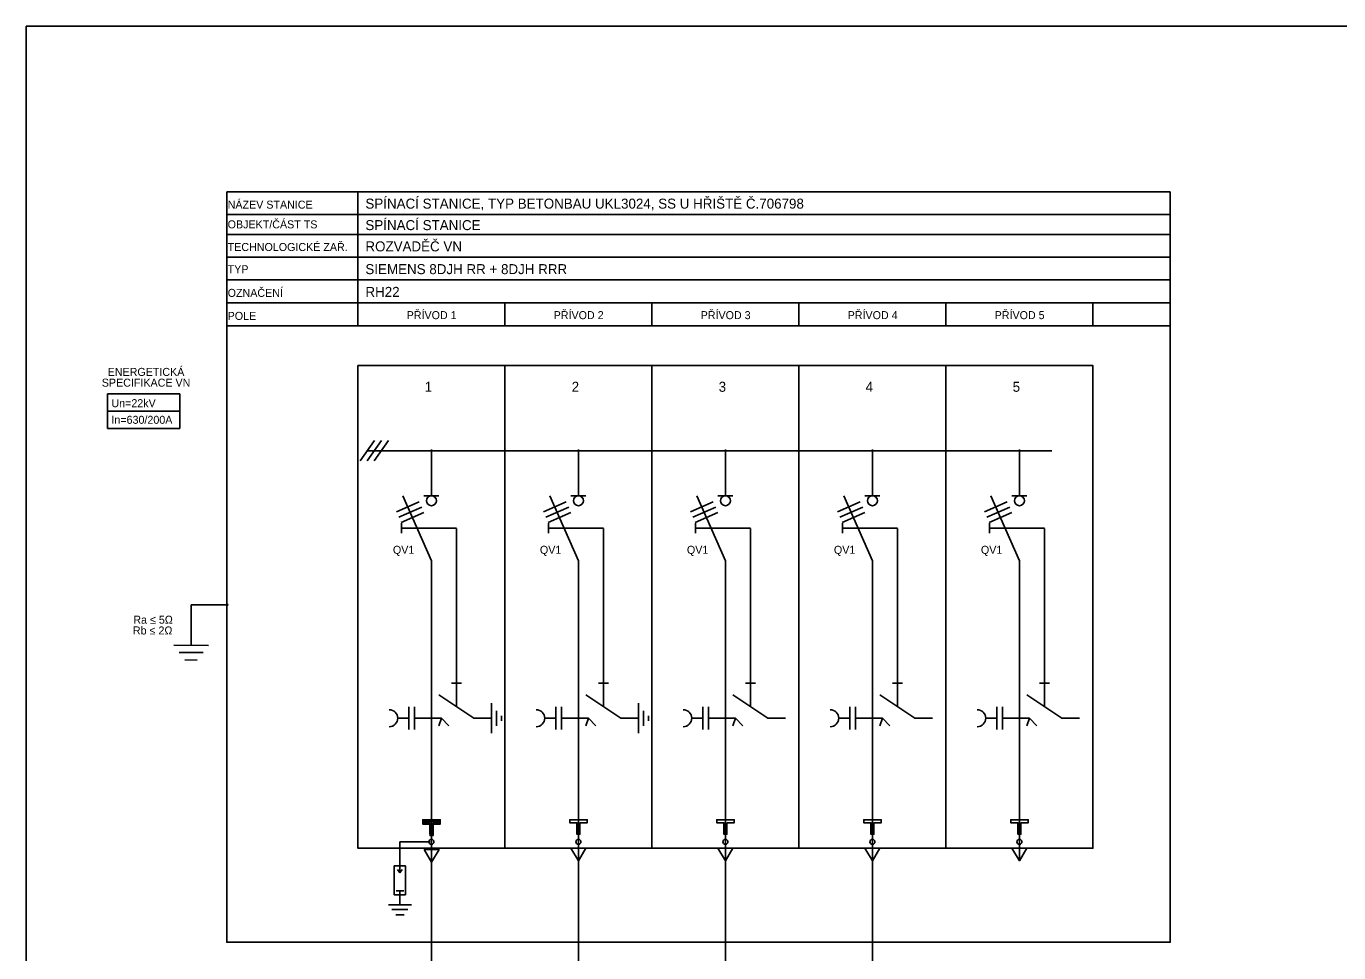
# Model space of a CAD drawing. Extents: x -540906 to -539838, y -1177786 to -1177461.
# Drawn here: x -540048 to -539943, y -1177711.4 to -1177637.3 of the extents above; entities that cross this region are included whole.
import ezdxf

# ---------------------------------------------------------------- set-up
doc = ezdxf.new("R2010")
doc.units = 0
for name, color, linetype in [('_RAZITKO', 7, 'Continuous'), ('FGVN_SCHEMA_VEDENI', 7, 'Continuous'), ('Implicitní', 7, 'Continuous'), ('nv_kabel_rozv_nove', 7, 'Continuous'), ('Popisky', 7, 'Continuous'), ('SILNÁ-ČÁRA', 7, 'Continuous'), ('SLABÁ-ČÁRA', 7, 'Continuous'), ('TEXT-NORMAL', 7, 'Continuous'), ('TEXT-TUČNÝ', 7, 'Continuous'), ('TEXT-TUČNÝ-eon', 7, 'Continuous'), ('ČÁRKOVANÁ', 7, 'Continuous')]:
    doc.layers.add(name, color=color, linetype=linetype)

msp = doc.modelspace()

# ---------------------------------------------------------------- linework, layer by layer
at = {"layer": 'FGVN_SCHEMA_VEDENI'}
for centre, start, end in [((-540015.54, -1177671.25), 0, 180), ((-540015.54, -1177671.25), 180, 0), ((-540003.78, -1177671.25), 0, 180), ((-540003.78, -1177671.25), 180, 0), ((-539992.02, -1177671.25), 0, 180), ((-539992.02, -1177671.25), 180, 0), ((-539980.26, -1177671.25), 0, 180), ((-539980.26, -1177671.25), 180, 0), ((-539968.5, -1177671.25), 0, 180), ((-539968.5, -1177671.25), 180, 0), ((-540031.87, -1177683.58), 0, 180), ((-540031.87, -1177683.58), 180, 0)]:
    msp.add_arc(centre, 0.05, start, end, dxfattribs=at)
at = {"layer": 'Implicitní'}
msp.add_lwpolyline([(-540047.95, -1177637.3), (-539837.95, -1177637.3), (-539837.95, -1177785.8), (-540047.95, -1177785.8)], close=True, dxfattribs=at)
at = {"layer": 'nv_kabel_rozv_nove'}
for p, q in [((-540031.88, -1177683.58), (-540034.76, -1177683.59)), ((-540034.76, -1177683.59), (-540034.76, -1177685.12)), ((-540034.76, -1177685.12), (-540034.76, -1177686.82)), ((-540033.38, -1177686.82), (-540036.14, -1177686.81)), ((-540033.81, -1177687.38), (-540035.72, -1177687.38)), ((-540034.27, -1177688), (-540035.26, -1177687.99))]:
    msp.add_line(p, q, dxfattribs=at)
at = {"layer": 'Popisky'}
for p, q in [((-540003.78, -1177704.05), (-540003.79, -1177722.08)), ((-539992.02, -1177704.05), (-539992.04, -1177740.12)), ((-539980.26, -1177704.05), (-539980.28, -1177740.12)), ((-540015.53, -1177704.15), (-540015.53, -1177723.88))]:
    msp.add_line(p, q, dxfattribs=at)
at = {"layer": 'SILNÁ-ČÁRA'}
for p, q in [((-540015.54, -1177673.25), (-540015.54, -1177671.25)), ((-540003.78, -1177673.25), (-540003.78, -1177671.25)), ((-539992.02, -1177673.25), (-539992.02, -1177671.25)), ((-539980.26, -1177673.25), (-539980.26, -1177671.25)), ((-539968.5, -1177673.25), (-539968.5, -1177671.25)), ((-540015.54, -1177674.85), (-540015.54, -1177673.25)), ((-540003.78, -1177674.85), (-540003.78, -1177673.25)), ((-539992.02, -1177674.85), (-539992.02, -1177673.25)), ((-539980.26, -1177674.85), (-539980.26, -1177673.25)), ((-539968.5, -1177674.85), (-539968.5, -1177673.25)), ((-540017.82, -1177674.85), (-540015.54, -1177680.05)), ((-540016.14, -1177674.85), (-540014.94, -1177674.85)), ((-540006.06, -1177674.85), (-540003.78, -1177680.05)), ((-540004.38, -1177674.85), (-540003.18, -1177674.85)), ((-539994.3, -1177674.85), (-539992.02, -1177680.05)), ((-539992.62, -1177674.85), (-539991.42, -1177674.85)), ((-539982.54, -1177674.85), (-539980.26, -1177680.05)), ((-539980.86, -1177674.85), (-539979.66, -1177674.85)), ((-539970.78, -1177674.85), (-539968.5, -1177680.05)), ((-539969.1, -1177674.85), (-539967.9, -1177674.85)), ((-540015.54, -1177680.05), (-540015.54, -1177681.65)), ((-540003.78, -1177680.05), (-540003.78, -1177681.65)), ((-539992.02, -1177680.05), (-539992.02, -1177681.65)), ((-539980.26, -1177680.05), (-539980.26, -1177681.65)), ((-539968.5, -1177680.05), (-539968.5, -1177681.65)), ((-540015.54, -1177681.65), (-540015.54, -1177704.05)), ((-540003.78, -1177681.65), (-540003.78, -1177704.05)), ((-539992.02, -1177681.65), (-539992.02, -1177704.05)), ((-539980.26, -1177681.65), (-539980.26, -1177704.05)), ((-539968.5, -1177681.65), (-539968.5, -1177704.05)), ((-540016.24, -1177700.77), (-540014.83, -1177700.77)), ((-540016.24, -1177700.77), (-540016.24, -1177701.01)), ((-540016.24, -1177700.77), (-540014.83, -1177700.77)), ((-540016.24, -1177700.77), (-540016.24, -1177701.01)), ((-540016.24, -1177700.88), (-540014.83, -1177700.88)), ((-540016.24, -1177700.88), (-540016.24, -1177701.11)), ((-540016.24, -1177700.88), (-540014.83, -1177700.88)), ((-540016.24, -1177700.88), (-540016.24, -1177701.11)), ((-540014.83, -1177700.77), (-540014.83, -1177701.01)), ((-540014.83, -1177700.77), (-540014.83, -1177701.01)), ((-540014.83, -1177700.88), (-540014.83, -1177701.11)), ((-540014.83, -1177700.88), (-540014.83, -1177701.11)), ((-540004.48, -1177700.77), (-540003.07, -1177700.77)), ((-540004.48, -1177700.77), (-540004.48, -1177701.01)), ((-540004.48, -1177700.77), (-540003.07, -1177700.77)), ((-540004.48, -1177700.77), (-540004.48, -1177701.01)), ((-540003.07, -1177700.77), (-540003.07, -1177701.01)), ((-540003.07, -1177700.77), (-540003.07, -1177701.01)), ((-539992.72, -1177700.77), (-539991.31, -1177700.77)), ((-539992.72, -1177700.77), (-539992.72, -1177701.01)), ((-539992.72, -1177700.77), (-539991.31, -1177700.77)), ((-539992.72, -1177700.77), (-539992.72, -1177701.01)), ((-539991.31, -1177700.77), (-539991.31, -1177701.01)), ((-539991.31, -1177700.77), (-539991.31, -1177701.01)), ((-539980.96, -1177700.77), (-539979.55, -1177700.77)), ((-539980.96, -1177700.77), (-539980.96, -1177701.01)), ((-539980.96, -1177700.77), (-539979.55, -1177700.77)), ((-539980.96, -1177700.77), (-539980.96, -1177701.01)), ((-539979.55, -1177700.77), (-539979.55, -1177701.01)), ((-539979.55, -1177700.77), (-539979.55, -1177701.01)), ((-539969.2, -1177700.77), (-539967.79, -1177700.77)), ((-539969.2, -1177700.77), (-539969.2, -1177701.01)), ((-539969.2, -1177700.77), (-539967.79, -1177700.77)), ((-539969.2, -1177700.77), (-539969.2, -1177701.01)), ((-539967.79, -1177700.77), (-539967.79, -1177701.01)), ((-539967.79, -1177700.77), (-539967.79, -1177701.01)), ((-540016.24, -1177701.01), (-540015.66, -1177701.01)), ((-540016.24, -1177701.01), (-540015.66, -1177701.01)), ((-540016.24, -1177701.11), (-540015.65, -1177701.11)), ((-540016.24, -1177701.11), (-540015.65, -1177701.11)), ((-540015.66, -1177701.01), (-540015.66, -1177701.93)), ((-540015.66, -1177701.01), (-540015.66, -1177701.93)), ((-540015.66, -1177701.01), (-540015.66, -1177701.93)), ((-540015.66, -1177701.01), (-540015.66, -1177701.93)), ((-540015.66, -1177701.93), (-540015.42, -1177701.93)), ((-540015.66, -1177701.93), (-540015.42, -1177701.93)), ((-540015.65, -1177701.11), (-540015.65, -1177702.03)), ((-540015.65, -1177701.11), (-540015.65, -1177702.03)), ((-540015.65, -1177701.11), (-540015.65, -1177702.03)), ((-540015.65, -1177701.11), (-540015.65, -1177702.03)), ((-540015.65, -1177702.03), (-540015.41, -1177702.03)), ((-540015.65, -1177702.03), (-540015.41, -1177702.03)), ((-540015.42, -1177701.01), (-540014.83, -1177701.01)), ((-540015.42, -1177701.01), (-540015.42, -1177701.93)), ((-540015.42, -1177701.01), (-540014.83, -1177701.01)), ((-540015.42, -1177701.01), (-540015.42, -1177701.93)), ((-540015.41, -1177701.11), (-540014.83, -1177701.11)), ((-540015.41, -1177701.11), (-540015.41, -1177702.03)), ((-540015.41, -1177701.11), (-540014.83, -1177701.11)), ((-540015.41, -1177701.11), (-540015.41, -1177702.03)), ((-540004.48, -1177701.01), (-540003.9, -1177701.01)), ((-540004.48, -1177701.01), (-540003.9, -1177701.01)), ((-540003.9, -1177701.01), (-540003.9, -1177701.93)), ((-540003.9, -1177701.01), (-540003.9, -1177701.93)), ((-540003.9, -1177701.01), (-540003.9, -1177701.93)), ((-540003.9, -1177701.01), (-540003.9, -1177701.93)), ((-540003.9, -1177701.93), (-540003.66, -1177701.93)), ((-540003.9, -1177701.93), (-540003.66, -1177701.93)), ((-540003.66, -1177701.01), (-540003.07, -1177701.01)), ((-540003.66, -1177701.01), (-540003.66, -1177701.93)), ((-540003.66, -1177701.01), (-540003.07, -1177701.01)), ((-540003.66, -1177701.01), (-540003.66, -1177701.93)), ((-539992.72, -1177701.01), (-539992.14, -1177701.01)), ((-539992.72, -1177701.01), (-539992.14, -1177701.01)), ((-539992.14, -1177701.01), (-539992.14, -1177701.93)), ((-539992.14, -1177701.01), (-539992.14, -1177701.93)), ((-539992.14, -1177701.01), (-539992.14, -1177701.93)), ((-539992.14, -1177701.01), (-539992.14, -1177701.93)), ((-539992.14, -1177701.93), (-539991.9, -1177701.93)), ((-539992.14, -1177701.93), (-539991.9, -1177701.93)), ((-539991.9, -1177701.01), (-539991.31, -1177701.01)), ((-539991.9, -1177701.01), (-539991.9, -1177701.93)), ((-539991.9, -1177701.01), (-539991.31, -1177701.01)), ((-539991.9, -1177701.01), (-539991.9, -1177701.93)), ((-539980.96, -1177701.01), (-539980.38, -1177701.01)), ((-539980.96, -1177701.01), (-539980.38, -1177701.01)), ((-539980.38, -1177701.01), (-539980.38, -1177701.93)), ((-539980.38, -1177701.01), (-539980.38, -1177701.93)), ((-539980.38, -1177701.01), (-539980.38, -1177701.93)), ((-539980.38, -1177701.01), (-539980.38, -1177701.93)), ((-539980.38, -1177701.93), (-539980.14, -1177701.93)), ((-539980.38, -1177701.93), (-539980.14, -1177701.93)), ((-539980.14, -1177701.01), (-539979.55, -1177701.01)), ((-539980.14, -1177701.01), (-539980.14, -1177701.93)), ((-539980.14, -1177701.01), (-539979.55, -1177701.01)), ((-539980.14, -1177701.01), (-539980.14, -1177701.93)), ((-539969.2, -1177701.01), (-539968.62, -1177701.01)), ((-539969.2, -1177701.01), (-539968.62, -1177701.01)), ((-539968.62, -1177701.01), (-539968.62, -1177701.93)), ((-539968.62, -1177701.01), (-539968.62, -1177701.93)), ((-539968.62, -1177701.01), (-539968.62, -1177701.93)), ((-539968.62, -1177701.01), (-539968.62, -1177701.93)), ((-539968.62, -1177701.93), (-539968.38, -1177701.93)), ((-539968.62, -1177701.93), (-539968.38, -1177701.93)), ((-539968.38, -1177701.01), (-539967.79, -1177701.01)), ((-539968.38, -1177701.01), (-539968.38, -1177701.93)), ((-539968.38, -1177701.01), (-539967.79, -1177701.01)), ((-539968.38, -1177701.01), (-539968.38, -1177701.93)), ((-540018.06, -1177703.16), (-540018.06, -1177705.02)), ((-540018.52, -1177704.45), (-540018.52, -1177706.77)), ((-540017.61, -1177704.45), (-540018.52, -1177704.45)), ((-540018.06, -1177705.02), (-540018.25, -1177704.76)), ((-540018.06, -1177705.02), (-540017.88, -1177704.76)), ((-540017.61, -1177704.45), (-540017.61, -1177706.77)), ((-540017.61, -1177706.77), (-540018.52, -1177706.77)), ((-540017.76, -1177706.45), (-540018.37, -1177706.45)), ((-540018.06, -1177706.45), (-540018.06, -1177707.58)), ((-540017.14, -1177707.58), (-540018.98, -1177707.58)), ((-540017.42, -1177707.95), (-540018.7, -1177707.95)), ((-540017.73, -1177708.37), (-540018.39, -1177708.37))]:
    msp.add_line(p, q, dxfattribs=at)
for points in [[(-540020.67, -1177671.25), (-539965.9, -1177671.25)], [(-540015.42, -1177701.01), (-540014.83, -1177701.01), (-540014.83, -1177700.77), (-540016.24, -1177700.77), (-540016.24, -1177701.01), (-540015.66, -1177701.01), (-540015.66, -1177701.93), (-540015.42, -1177701.93), (-540015.42, -1177701.01)], [(-540015.41, -1177701.11), (-540014.83, -1177701.11), (-540014.83, -1177700.88), (-540016.24, -1177700.88), (-540016.24, -1177701.11), (-540015.65, -1177701.11), (-540015.65, -1177702.03), (-540015.41, -1177702.03), (-540015.41, -1177701.11)], [(-540003.66, -1177701.01), (-540003.07, -1177701.01), (-540003.07, -1177700.77), (-540004.48, -1177700.77), (-540004.48, -1177701.01), (-540003.9, -1177701.01), (-540003.9, -1177701.93), (-540003.66, -1177701.93), (-540003.66, -1177701.01)], [(-539991.9, -1177701.01), (-539991.31, -1177701.01), (-539991.31, -1177700.77), (-539992.72, -1177700.77), (-539992.72, -1177701.01), (-539992.14, -1177701.01), (-539992.14, -1177701.93), (-539991.9, -1177701.93), (-539991.9, -1177701.01)], [(-539980.14, -1177701.01), (-539979.55, -1177701.01), (-539979.55, -1177700.77), (-539980.96, -1177700.77), (-539980.96, -1177701.01), (-539980.38, -1177701.01), (-539980.38, -1177701.93), (-539980.14, -1177701.93), (-539980.14, -1177701.01)], [(-539968.38, -1177701.01), (-539967.79, -1177701.01), (-539967.79, -1177700.77), (-539969.2, -1177700.77), (-539969.2, -1177701.01), (-539968.62, -1177701.01), (-539968.62, -1177701.93), (-539968.38, -1177701.93), (-539968.38, -1177701.01)], [(-540015.65, -1177702.54), (-540018.06, -1177702.54), (-540018.06, -1177703.16)]]:
    msp.add_lwpolyline(points, dxfattribs=at)
for points in [[(-540004.38, -1177703.05), (-540003.18, -1177703.05), (-540003.78, -1177704.05)], [(-539992.62, -1177703.05), (-539991.42, -1177703.05), (-539992.02, -1177704.05)], [(-539980.86, -1177703.05), (-539979.66, -1177703.05), (-539980.26, -1177704.05)], [(-539969.1, -1177703.05), (-539967.9, -1177703.05), (-539968.5, -1177704.05)], [(-540016.13, -1177703.15), (-540014.93, -1177703.15), (-540015.53, -1177704.15)]]:
    msp.add_lwpolyline(points, close=True, dxfattribs=at)
for centre, radius in [((-540015.54, -1177675.25), 0.4), ((-540003.78, -1177675.25), 0.4), ((-539992.02, -1177675.25), 0.4), ((-539980.26, -1177675.25), 0.4), ((-539968.5, -1177675.25), 0.4), ((-540015.54, -1177702.54), 0.2), ((-540015.54, -1177702.54), 0.2), ((-540003.78, -1177702.54), 0.2), ((-540003.78, -1177702.54), 0.2), ((-539992.02, -1177702.54), 0.2), ((-539992.02, -1177702.54), 0.2), ((-539980.26, -1177702.54), 0.2), ((-539980.26, -1177702.54), 0.2), ((-539968.5, -1177702.54), 0.2), ((-539968.5, -1177702.54), 0.2)]:
    msp.add_circle(centre, radius, dxfattribs=at)
at = {"layer": 'SLABÁ-ČÁRA'}
for p, q in [((-540031.92, -1177650.54), (-539956.44, -1177650.54)), ((-540031.92, -1177650.54), (-540031.92, -1177661.26)), ((-540021.42, -1177661.26), (-540021.42, -1177650.54)), ((-539956.44, -1177661.26), (-539956.44, -1177650.54)), ((-540031.92, -1177652.36), (-539956.44, -1177652.36)), ((-540031.92, -1177653.95), (-539956.44, -1177653.95)), ((-540031.92, -1177655.77), (-539956.44, -1177655.77)), ((-540031.92, -1177657.59), (-539956.44, -1177657.59)), ((-540031.84, -1177659.43), (-539956.44, -1177659.43)), ((-540009.66, -1177661.26), (-540009.66, -1177659.43)), ((-539997.9, -1177661.26), (-539997.9, -1177659.43)), ((-539986.14, -1177661.26), (-539986.14, -1177659.43)), ((-539974.38, -1177661.26), (-539974.38, -1177659.43)), ((-539962.62, -1177661.26), (-539962.62, -1177659.43)), ((-540031.92, -1177661.26), (-539956.44, -1177661.26)), ((-540021.25, -1177672.07), (-540020.1, -1177670.43)), ((-540020.69, -1177672.07), (-540019.54, -1177670.43)), ((-540020.12, -1177672.07), (-540018.98, -1177670.43)), ((-540018.34, -1177676.15), (-540016.51, -1177675.34)), ((-540018.15, -1177676.58), (-540016.32, -1177675.77)), ((-540006.58, -1177676.15), (-540004.75, -1177675.34)), ((-540006.39, -1177676.58), (-540004.56, -1177675.77)), ((-539994.82, -1177676.15), (-539992.99, -1177675.34)), ((-539994.63, -1177676.58), (-539992.8, -1177675.77)), ((-539983.06, -1177676.15), (-539981.23, -1177675.34)), ((-539982.87, -1177676.58), (-539981.04, -1177675.77)), ((-539971.3, -1177676.15), (-539969.47, -1177675.34)), ((-539971.11, -1177676.58), (-539969.28, -1177675.77)), ((-540017.97, -1177677), (-540016.14, -1177676.19)), ((-540006.21, -1177677), (-540004.38, -1177676.19)), ((-539994.45, -1177677), (-539992.62, -1177676.19)), ((-539982.69, -1177677), (-539980.86, -1177676.19)), ((-539970.93, -1177677), (-539969.1, -1177676.19)), ((-540017.94, -1177677.05), (-540017.94, -1177677.85)), ((-540017.94, -1177677.45), (-540016.68, -1177677.45)), ((-540016.68, -1177677.45), (-540013.54, -1177677.45)), ((-540013.54, -1177689.85), (-540013.54, -1177677.47)), ((-540006.18, -1177677.05), (-540006.18, -1177677.85)), ((-540006.18, -1177677.45), (-540004.92, -1177677.45)), ((-540004.92, -1177677.45), (-540001.78, -1177677.45)), ((-540001.78, -1177689.85), (-540001.78, -1177677.47)), ((-539994.42, -1177677.05), (-539994.42, -1177677.85)), ((-539994.42, -1177677.45), (-539993.16, -1177677.45)), ((-539993.16, -1177677.45), (-539990.02, -1177677.45)), ((-539990.02, -1177689.85), (-539990.02, -1177677.47)), ((-539982.66, -1177677.05), (-539982.66, -1177677.85)), ((-539982.66, -1177677.45), (-539981.4, -1177677.45)), ((-539981.4, -1177677.45), (-539978.26, -1177677.45)), ((-539978.26, -1177689.85), (-539978.26, -1177677.47)), ((-539970.9, -1177677.05), (-539970.9, -1177677.85)), ((-539970.9, -1177677.45), (-539969.64, -1177677.45)), ((-539969.64, -1177677.45), (-539966.5, -1177677.45)), ((-539966.5, -1177689.85), (-539966.5, -1177677.47)), ((-540013.14, -1177689.85), (-540013.94, -1177689.85)), ((-540013.54, -1177691.71), (-540013.54, -1177689.85)), ((-540001.38, -1177689.85), (-540002.18, -1177689.85)), ((-540001.78, -1177691.71), (-540001.78, -1177689.85)), ((-539989.62, -1177689.85), (-539990.42, -1177689.85)), ((-539990.02, -1177691.71), (-539990.02, -1177689.85)), ((-539977.86, -1177689.85), (-539978.66, -1177689.85)), ((-539978.26, -1177691.71), (-539978.26, -1177689.85)), ((-539966.1, -1177689.85), (-539966.9, -1177689.85)), ((-539966.5, -1177691.71), (-539966.5, -1177689.85)), ((-540014.94, -1177690.77), (-540012.14, -1177692.65)), ((-540010.74, -1177691.45), (-540010.74, -1177693.85)), ((-540003.18, -1177690.77), (-540000.38, -1177692.65)), ((-539998.98, -1177691.45), (-539998.98, -1177693.85)), ((-539991.42, -1177690.77), (-539988.62, -1177692.65)), ((-539979.66, -1177690.77), (-539976.86, -1177692.65)), ((-539967.9, -1177690.77), (-539965.1, -1177692.65)), ((-540017.34, -1177691.75), (-540017.34, -1177693.55)), ((-540016.89, -1177691.75), (-540016.89, -1177693.55)), ((-540010.34, -1177692.05), (-540010.34, -1177693.25)), ((-540009.94, -1177692.45), (-540009.94, -1177692.85)), ((-540005.58, -1177691.75), (-540005.58, -1177693.55)), ((-540005.13, -1177691.75), (-540005.13, -1177693.55)), ((-539998.58, -1177692.05), (-539998.58, -1177693.25)), ((-539998.18, -1177692.45), (-539998.18, -1177692.85)), ((-539993.82, -1177691.75), (-539993.82, -1177693.55)), ((-539993.37, -1177691.75), (-539993.37, -1177693.55)), ((-539982.06, -1177691.75), (-539982.06, -1177693.55)), ((-539981.61, -1177691.75), (-539981.61, -1177693.55)), ((-539970.3, -1177691.75), (-539970.3, -1177693.55)), ((-539969.85, -1177691.75), (-539969.85, -1177693.55)), ((-540018.24, -1177692.65), (-540017.34, -1177692.65)), ((-540016.89, -1177692.65), (-540015.54, -1177692.65)), ((-540015.54, -1177692.65), (-540014.74, -1177692.65)), ((-540014.96, -1177693.25), (-540014.74, -1177692.65)), ((-540014.14, -1177693.25), (-540014.74, -1177692.65)), ((-540010.74, -1177692.65), (-540012.14, -1177692.65)), ((-540006.48, -1177692.65), (-540005.58, -1177692.65)), ((-540005.13, -1177692.65), (-540003.78, -1177692.65)), ((-540003.78, -1177692.65), (-540002.98, -1177692.65)), ((-540003.2, -1177693.25), (-540002.98, -1177692.65)), ((-540002.38, -1177693.25), (-540002.98, -1177692.65)), ((-539998.98, -1177692.65), (-540000.38, -1177692.65)), ((-539994.72, -1177692.65), (-539993.82, -1177692.65)), ((-539993.37, -1177692.65), (-539992.02, -1177692.65)), ((-539992.02, -1177692.65), (-539991.22, -1177692.65)), ((-539991.44, -1177693.25), (-539991.22, -1177692.65)), ((-539990.62, -1177693.25), (-539991.22, -1177692.65)), ((-539987.22, -1177692.65), (-539988.62, -1177692.65)), ((-539982.96, -1177692.65), (-539982.06, -1177692.65)), ((-539981.61, -1177692.65), (-539980.26, -1177692.65)), ((-539980.26, -1177692.65), (-539979.46, -1177692.65)), ((-539979.68, -1177693.25), (-539979.46, -1177692.65)), ((-539978.86, -1177693.25), (-539979.46, -1177692.65)), ((-539975.46, -1177692.65), (-539976.86, -1177692.65)), ((-539971.2, -1177692.65), (-539970.3, -1177692.65)), ((-539969.85, -1177692.65), (-539968.5, -1177692.65)), ((-539968.5, -1177692.65), (-539967.7, -1177692.65)), ((-539967.92, -1177693.25), (-539967.7, -1177692.65)), ((-539967.1, -1177693.25), (-539967.7, -1177692.65)), ((-539963.7, -1177692.65), (-539965.1, -1177692.65))]:
    msp.add_line(p, q, dxfattribs=at)
msp.add_lwpolyline([(-540031.92, -1177661.26), (-539956.44, -1177661.26), (-539956.44, -1177710.57), (-540031.92, -1177710.57)], close=True, dxfattribs=at)
for centre in [(-540018.91, -1177692.65), (-540007.15, -1177692.65), (-539995.39, -1177692.65), (-539983.63, -1177692.65), (-539971.87, -1177692.65)]:
    msp.add_arc(centre, 0.675, 270, 90, dxfattribs=at)
at = {"layer": 'TEXT-NORMAL'}
for p, q in [((-540041.46, -1177666.71), (-540041.46, -1177669.48)), ((-540041.46, -1177666.71), (-540035.67, -1177666.71)), ((-540035.67, -1177666.71), (-540035.67, -1177669.48)), ((-540041.46, -1177668.09), (-540035.67, -1177668.09)), ((-540041.46, -1177669.48), (-540035.67, -1177669.48))]:
    msp.add_line(p, q, dxfattribs=at)
at = {"layer": 'ČÁRKOVANÁ'}
for points in [[(-540021.42, -1177664.45), (-540009.66, -1177664.45), (-540009.66, -1177703.05), (-540021.42, -1177703.05)], [(-540009.66, -1177664.45), (-539997.9, -1177664.45), (-539997.9, -1177703.05), (-540009.66, -1177703.05)], [(-539997.9, -1177664.45), (-539986.14, -1177664.45), (-539986.14, -1177703.05), (-539997.9, -1177703.05)], [(-539986.14, -1177664.45), (-539974.38, -1177664.45), (-539974.38, -1177703.05), (-539986.14, -1177703.05)], [(-539974.38, -1177664.45), (-539962.62, -1177664.45), (-539962.62, -1177703.05), (-539974.38, -1177703.05)]]:
    msp.add_lwpolyline(points, close=True, dxfattribs=at)

# ---------------------------------------------------------------- texts
at = {"layer": '_RAZITKO'}
for s, p in [('NÁZEV STANICE', (-540031.84, -1177651.89)), ('OBJEKT/ČÁST TS', (-540031.84, -1177653.47)), ('TECHNOLOGICKÉ ZAŘ.', (-540031.84, -1177655.28)), ('TYP', (-540031.84, -1177657.06)), ('OZNAČENÍ', (-540031.84, -1177658.95)), ('POLE', (-540031.84, -1177660.79)), ('ENERGETICKÁ ', (-540041.44, -1177665.27)), ('SPECIFIKACE VN', (-540041.91, -1177666.13))]:
    msp.add_text(s, height=0.64, dxfattribs=at).set_placement(p)
at = {"layer": 'TEXT-NORMAL'}
for s, height, p in [('SPÍNACÍ STANICE', 0.8, (-540020.82, -1177653.61)), ('ROZVADĚČ VN', 0.8, (-540020.82, -1177655.31)), ('SIEMENS 8DJH RR + 8DJH RRR', 0.8, (-540020.82, -1177657.13)), ('PŘÍVOD 1', 0.64, (-540017.52, -1177660.73)), ('PŘÍVOD 2', 0.64, (-540005.76, -1177660.73)), ('PŘÍVOD 3', 0.64, (-539994, -1177660.73)), ('PŘÍVOD 4', 0.64, (-539982.24, -1177660.73)), ('PŘÍVOD 5', 0.64, (-539970.48, -1177660.73)), ('Un=22kV', 0.64, (-540041.14, -1177667.77)), ('In=630/200A', 0.64, (-540041.14, -1177669.1)), ('QV1', 0.64, (-540018.62, -1177679.5)), ('QV1', 0.64, (-540006.86, -1177679.5)), ('QV1', 0.64, (-539995.1, -1177679.5)), ('QV1', 0.64, (-539983.34, -1177679.5)), ('QV1', 0.64, (-539971.58, -1177679.5))]:
    msp.add_text(s, height=height, rotation=0, dxfattribs=at).set_placement(p)
at = {"layer": 'TEXT-TUČNÝ'}
for s, p in [('Ra ≤ 5Ω', (-540039.39, -1177685.09)), ('Rb ≤ 2Ω', (-540039.42, -1177685.95))]:
    msp.add_text(s, height=0.641, dxfattribs=at).set_placement(p)
at = {"layer": 'TEXT-TUČNÝ-eon'}
for s, p in [('SPÍNACÍ STANICE, TYP BETONBAU UKL3024, SS U HŘIŠTĚ Č.706798', (-540020.82, -1177651.89)), ('RH22', (-540020.82, -1177658.95)), ('1', (-540016.08, -1177666.54)), ('2', (-540004.32, -1177666.54)), ('3', (-539992.56, -1177666.54)), ('4', (-539980.8, -1177666.54)), ('5', (-539969.04, -1177666.54))]:
    msp.add_text(s, height=0.8, dxfattribs=at).set_placement(p)

doc.saveas('drawing.dxf')
